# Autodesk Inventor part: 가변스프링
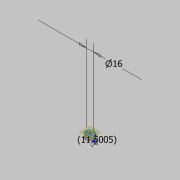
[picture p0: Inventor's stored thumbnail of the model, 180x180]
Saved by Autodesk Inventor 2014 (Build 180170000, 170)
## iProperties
Created: 2015-04
Part Number: 가변스프링
Material: 강철, 탄소
Document SubType Name: Modeling
Designer: Administrator
Density: 7.87 g/cm^3
Appearance: 반연마
Mass: 4.78743 g
Surface Area: 12.5262 cm^2
Volume: 0.608313 cm^3
Author: Administrator
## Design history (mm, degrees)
sketch "스케치1"
  geometry: L1 (0, 0)-(8, 0); L2 (8, 0)-(8, 11.5); L3 (8, 11.5)-(0, 11.5); L4 (0, 11.5)-(0, 0); C1 r 1 at (8, 0)
  constraints: 8 end point, 2 parallel, 1 centre point, 1 coincident, 1 horizontal, 1 perpendicular
  dimensions: "d0" = 16 diameter of L2 L4; "d1" = 11.50049 distance between parallel lines of L1 L3 (derived); "d2" = 2 diameter of C1
feature "코일1" pitch "d3" = 10; turns "d5" = 4; dims "d4" = 11.50049 (= d1), "d6" = 0, angle "d7" = 90 deg, angle "d8" = 90 deg, "d9" = 0, "d10" = 0
sketch "스케치2"
  geometry: L1 (-9, 0)-(-7, 0) reference; 1 further point
  constraints: 1 horizontal alignment
extrude "돌출1" cut sketch "스케치2" stored distance "d11" = 10; taper "d12" = 0 deg
node "작업 평면1"
sketch "스케치3"
  geometry: L1 (9, 0)-(7, 0) reference; 1 further point
  constraints: 1 horizontal alignment
extrude "돌출2" cut sketch "스케치3" stored distance "d13" = 10; taper "d14" = 0 deg
node "솔리드1"
node "절단 모서리 투영1"
node "절단 모서리 투영2"
